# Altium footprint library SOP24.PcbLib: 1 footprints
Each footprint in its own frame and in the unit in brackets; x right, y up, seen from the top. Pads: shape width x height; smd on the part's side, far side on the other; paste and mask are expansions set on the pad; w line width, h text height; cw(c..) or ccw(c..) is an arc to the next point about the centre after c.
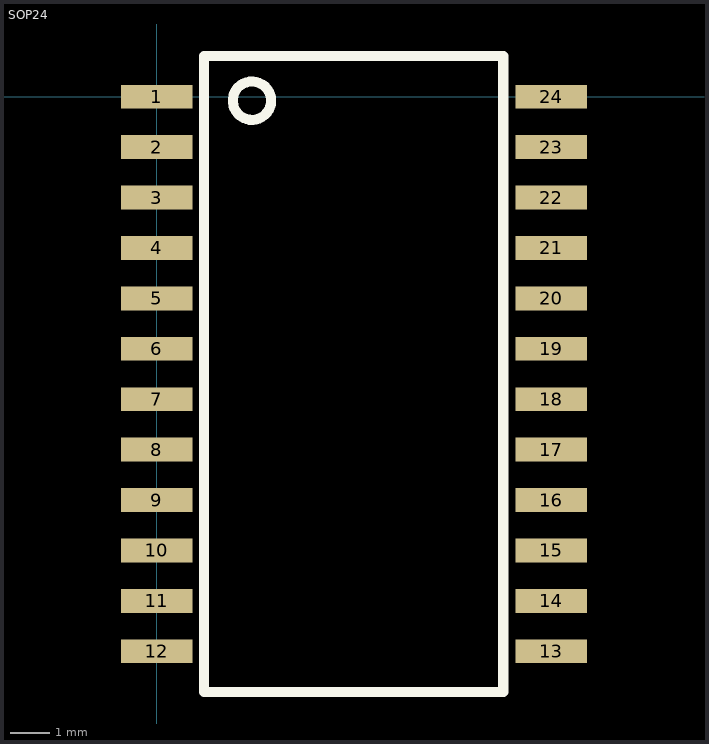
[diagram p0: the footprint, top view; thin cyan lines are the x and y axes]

## SOP24 [mm]
pads (24):
  rect 1.8x0.6 smd: 1(0,0) 2(0,-1.27) 3(0,-2.54) 4(0,-3.81) 5(0,-5.08) 6(0,-6.35) 7(0,-7.62) 8(0,-8.89) 9(0,-10.16) 10(0,-11.43) 11(0,-12.7) 12(0,-13.97) 13(9.94,-13.97) 14(9.94,-12.7) 15(9.94,-11.43) 16(9.94,-10.16) 17(9.94,-8.89) 18(9.94,-7.62) 19(9.94,-6.35) 20(9.94,-5.08) 21(9.94,-3.81) 22(9.94,-2.54) 23(9.94,-1.27) 24(9.94,0)
Top Overlay:
  circle w0.254: c2.4,-0.1 r0.484
  lines w0.254: 1.19,-15 1.19,1.03 8.73,1.03 8.73,-15 1.19,-15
